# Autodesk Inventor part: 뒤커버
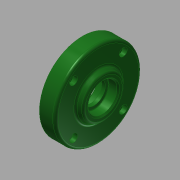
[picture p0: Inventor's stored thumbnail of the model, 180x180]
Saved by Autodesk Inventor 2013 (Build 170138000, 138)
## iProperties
Company: 한국ATC센터
Created: 2015-12
Part Number: 뒤커버
Document SubType Name: Modeling
Designer: mdu
Density: 2.71 g/cm^3
Mass: 97.9591 g
Surface Area: 115.525 cm^2
Volume: 36.1473 cm^3
Material: 알루미늄-6061
Author: mdu
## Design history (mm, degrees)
sketch "스케치1"
  geometry: L1 (-10.5, 0)-(10.5, 0); L2 (10.5, 0)-(10.5, 22.5); L3 (10.5, 22.5)-(5.5, 22.5); L4 (5.5, 22.5)-(5.5, 32.5); L5 (5.5, 32.5)-(-6.5, 32.5); L6 (-6.5, 32.5)-(-6.5, 17.5); L7 (-6.5, 17.5)-(-10.5, 15.191); L8 (-10.5, 15.191)-(-10.5, 0); 2 further points
  constraints: 16 end point, 3 parallel, 3 perpendicular, 1 coincident, 1 horizontal, 1 midpoint
  dimensions: "d0" = 21 distance of L1.start L1.end; "d1" = 65 diameter of L5 L1; "d2" = 45 diameter of L3 L1; "d3" = 35 diameter of L6.end L1; "d4" = 120 deg angle of L7 L6; "d5" = 12 distance of L4.end L5.end; "d6" = 5 distance of L2.end L3.end
revolve "회전1" sketch "스케치1" stored, may be unused: angle "d7" = 90 deg
sketch "스케치2"
  geometry: L1 (0, 0)-(32.5, 0); L2 (0, 0)-(18.738, 18.738); 1 further point
  constraints: 4 end point, 1 horizontal, 1 horizontal alignment, 1 other
  dimensions: "d8" = 45 deg angle of L1 L2; "d9" = 26.5 distance of L1.start L2.end
hole "구멍1" sketch "스케치2" at (18.738, 18.738) diameter "d10" = 3.4; stored, may be unused: countersink angle "d14" = 90 deg, drill point angle "d16" = 118 deg; dims "d11" = 6, "d12" = 6, "d13" = 3.3, "d15" = 8
fillet "모깎기1" dims "d20" = 2
hole "구멍2" diameter "d23" = 15; stored, may be unused: countersink angle "d27" = 90 deg, drill point angle "d29" = 0 deg; dims "d21" = 10, "d22" = 10, "d24" = 6, "d25" = 35, "d26" = 11, "d28" = 14
chamfer "모따기1" distance "d39" = 1; stored, may be unused: second distance "d40" = 2, angle "d41" = 45 deg
fillet "모깎기2" dims "d42" = 0.3
hole "구멍4" diameter "d46" = 17; stored, may be unused: countersink angle "d50" = 90 deg, drill point angle "d52" = 118 deg; dims "d44" = 10, "d45" = 10, "d47" = 6, "d48" = 22, "d49" = 7.3, "d51" = 8
chamfer "모따기2" distance "d53" = 1; stored, may be unused: second distance "d54" = 2, angle "d55" = 45 deg
fillet "모깎기3" dims "d56" = 0.3
node "작업 평면1"
sketch "스케치3"
  geometry: 2 further points
  constraints: 1 coincident, 1 other
feature "엠보싱1" sketch "스케치3" dims "d0" = 21, "d1" = 65, "d2" = 45, "d3" = 35, "d4" = 120 deg, "d5" = 12, "d6" = 5, "d58" = 0.3, "d59" = 0
fillet "모깎기4" dims "d60" = 0.2
fillet "모깎기5" dims "d61" = 0.1
node "솔리드1"
pattern_circular "원형 패턴1" dims angle "d18" = 360 deg
